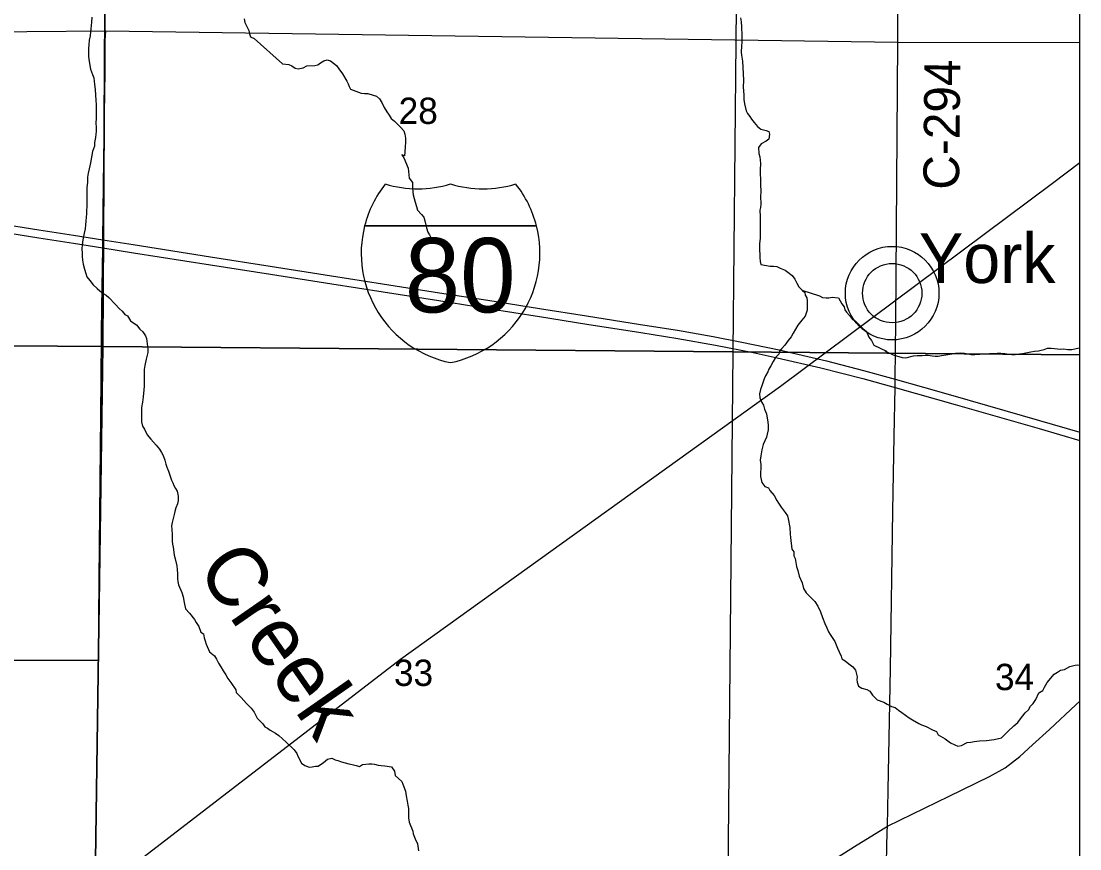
# Model space of a CAD drawing. Extents: x -8.5 to 18.7, y -20.3 to 7.
# Drawn here: x 15.375 to 18.741, y 1.627 to 4.26 of the extents above; entities that cross this region are included whole.
import ezdxf

# ---------------------------------------------------------------- set-up
doc = ezdxf.new("R2010")
doc.units = 0
for name, color, linetype in [('Default', 7, 'Continuous'), ('GM_X_Corporation', 7, 'Continuous'), ('GM_X_County_Road', 7, 'Continuous'), ('GM_X_County_Road_Text', 7, 'Continuous'), ('GM_X_Interstate_Location', 7, 'Continuous'), ('GM_X_Interstate_Route', 7, 'Continuous'), ('GM_X_Interstate_Shield', 7, 'Continuous'), ('GM_X_Minor_River', 7, 'Continuous'), ('GM_X_Minor_River_Text', 7, 'Continuous'), ('GM_X_Rail_Line', 7, 'Continuous'), ('GM_X_Section', 7, 'Continuous'), ('GM_X_Section_Text', 7, 'Continuous'), ('GM_X_State_Route', 7, 'Continuous'), ('GM_X_Township_Road', 7, 'Continuous'), ('GM_X_Unincorporated', 7, 'Continuous'), ('GM_X_Unincorporated_Location', 7, 'Continuous'), ('GM_X_Unincorporated_Text', 7, 'Continuous'), ('SH_Cut_Line', 7, 'Continuous')]:
    doc.layers.add(name, color=color, linetype=linetype)

msp = doc.modelspace()

# ---------------------------------------------------------------- linework, layer by layer
at = {"layer": 'Default'}
for points in [[(18.7413, 3.1985), (18.7413, 5.1812), (17.6568, 5.1811), (17.6382, 3.208)], [(18.7413, 1.196), (18.7413, 3.1985), (17.6382, 3.208), (17.6187, 1.2053)]]:
    msp.add_lwpolyline(points, close=True, dxfattribs=at)
at = {"layer": 'GM_X_Corporation'}
msp.add_lwpolyline([(18.7413, 1.1834), (18.7413, 6.938), (11.7049, 6.938), (11.6732, 5.0475), (11.6689, 4.6186), (11.6686, 4.5917), (11.6653, 4.2586), (11.64, 3.2551), (11.6132, 2.2462), (11.5871, 1.2389), (13.587, 1.2234), (15.5804, 1.208), (17.3261, 1.1944), (18.0915, 1.1885)], close=True, dxfattribs=at)
at = {"layer": 'GM_X_County_Road'}
for points in [[(18.1302, 1.6994), (18.1318, 1.8143), (18.1389, 2.2013), (18.1465, 2.7014), (18.1506, 2.9396), (18.1537, 3.095), (18.1543, 3.1212), (18.1565, 3.3035), (18.1628, 4.1924), (18.1717, 5.8471), (18.1598, 6.938)], [(18.1003, 1.2079), (18.1028, 1.2134), (18.1171, 1.2442), (18.1227, 1.2661), (18.1241, 1.304), (18.1261, 1.4721), (18.1267, 1.5823), (18.1273, 1.6332), (18.1285, 1.6812), (18.1302, 1.6994)]]:
    msp.add_lwpolyline(points, dxfattribs=at)
at = {"layer": 'GM_X_Interstate_Route'}
for points in [[(15.2513, 3.6247), (15.4311, 3.5964), (15.5415, 3.579), (15.6351, 3.5645), (15.7311, 3.549), (15.9769, 3.5106), (16.1667, 3.4809), (16.3624, 3.4499), (16.5241, 3.4243), (16.705, 3.3957), (16.8596, 3.3719), (17.0229, 3.3463), (17.1727, 3.3224), (17.344, 3.2954), (17.4621, 3.2766), (17.5754, 3.2566), (17.6667, 3.2389), (17.7858, 3.2139), (17.936, 3.179), (18.0537, 3.149), (18.1543, 3.1212), (18.2447, 3.0951), (18.3302, 3.0709), (18.4475, 3.0374), (18.6134, 2.9894), (18.7413, 2.9528)], [(15.2523, 3.5988), (15.4321, 3.5705), (15.5415, 3.5537), (15.6346, 3.5389), (15.7321, 3.5231), (15.9779, 3.4847), (16.1677, 3.455), (16.3635, 3.424), (16.5267, 3.3986), (16.7029, 3.371), (16.8606, 3.346), (17.0239, 3.3204), (17.1737, 3.2965), (17.3451, 3.2694), (17.4631, 3.2506), (17.5828, 3.2292), (17.7027, 3.2055), (17.779, 3.1891), (17.9174, 3.1571), (18.0518, 3.1233), (18.1537, 3.095), (18.3446, 3.04), (18.6122, 2.964), (18.7413, 2.9264)]]:
    msp.add_lwpolyline(points, dxfattribs=at)
at = {"layer": 'GM_X_Interstate_Shield'}
for p, q in [((16.4673, 3.6086), (17.0138, 3.6086)), ((17.0138, 3.6086), (16.4673, 3.6086)), ((17.0138, 3.6086), (16.4673, 3.6086))]:
    msp.add_line(p, q, dxfattribs=at)
for centre, start, end in [((16.8116, 3.5215), 141.669, 165.8066), ((16.6368, 4.0814), 253.0091, 286.9909), ((16.8443, 4.0814), 253.0091, 286.9909), ((16.6695, 3.5215), 14.1934, 38.331), ((16.8116, 3.5215), 165.8066, 258.463), ((16.6695, 3.5215), 281.537, 14.1934)]:
    msp.add_arc(centre, 0.3551, start, end, dxfattribs=at)
at = {"layer": 'GM_X_Minor_River'}
msp.add_line((18.7353, 2.212), (18.7413, 2.2119), dxfattribs=at)
for points in [[(15.6001, 4.2721), (15.5986, 4.2561), (15.5979, 4.2462), (15.5972, 4.2356), (15.5957, 4.2257), (15.5943, 4.2135), (15.5921, 4.1991), (15.5906, 4.1846), (15.5892, 4.1725), (15.5892, 4.1634), (15.59, 4.1489), (15.5909, 4.1391), (15.5924, 4.1246), (15.5963, 4.1072), (15.6017, 4.0905), (15.6063, 4.0791), (15.6079, 4.0692), (15.6087, 4.0586), (15.6103, 4.0427), (15.6119, 4.0244), (15.6128, 4.0085), (15.6136, 3.9933), (15.6138, 3.9523), (15.6131, 3.934), (15.614, 3.9234), (15.614, 3.909), (15.6126, 3.8998), (15.6118, 3.89), (15.6089, 3.874), (15.6082, 3.8626), (15.6022, 3.8451), (15.5963, 3.8086), (15.5918, 3.7903), (15.5881, 3.7759), (15.5867, 3.7637), (15.586, 3.7478), (15.5846, 3.7295), (15.5839, 3.7151), (15.5839, 3.7045), (15.5847, 3.6961), (15.584, 3.6847), (15.5841, 3.6695), (15.5834, 3.6589), (15.5827, 3.6467), (15.582, 3.6368), (15.5813, 3.6231), (15.5798, 3.6117), (15.5784, 3.5996), (15.5762, 3.5851), (15.571, 3.5638), (15.5695, 3.5479), (15.5688, 3.5357), (15.5689, 3.522), (15.5697, 3.5114), (15.5705, 3.4993), (15.5721, 3.4871), (15.5767, 3.4712), (15.5814, 3.4568), (15.5837, 3.4461), (15.5936, 3.4348), (15.6043, 3.4212), (15.6173, 3.4098), (15.6257, 3.4015), (15.6363, 3.3932), (15.6455, 3.3879), (15.6539, 3.3804), (15.6745, 3.36), (15.6875, 3.3456), (15.6966, 3.3373), (15.705, 3.3267), (15.7134, 3.3229), (15.7233, 3.307), (15.7332, 3.2995), (15.7424, 3.2934), (15.7523, 3.2805), (15.7622, 3.2715), (15.7706, 3.2594), (15.7737, 3.2503), (15.7784, 3.2169), (15.7777, 3.2055), (15.7733, 3.1849), (15.7681, 3.1644), (15.7666, 3.1522), (15.766, 3.1325), (15.766, 3.1157), (15.7661, 3.099), (15.7654, 3.0876), (15.7633, 3.0648), (15.7611, 3.0481), (15.7581, 3.0306), (15.7582, 3.0185), (15.7575, 2.9964), (15.7576, 2.9858), (15.7615, 2.9714), (15.7676, 2.9623), (15.776, 2.9441), (15.7875, 2.9297), (15.805, 2.9116)], [(16.0845, 4.2668), (16.0868, 4.2554), (16.0929, 4.2425), (16.0991, 4.2304), (16.1014, 4.219), (16.1045, 4.2099), (16.1159, 4.2046), (16.2059, 4.1245), (16.2264, 4.1216), (16.2363, 4.1178), (16.247, 4.1103), (16.2561, 4.108), (16.272, 4.1111), (16.2841, 4.118), (16.3092, 4.1182), (16.3183, 4.1205), (16.3266, 4.1273), (16.3379, 4.1335), (16.3478, 4.1366), (16.3584, 4.1336), (16.3775, 4.1192), (16.3859, 4.1079), (16.3974, 4.092), (16.4104, 4.0692), (16.415, 4.0602), (16.4181, 4.0518), (16.4227, 4.0435), (16.4569, 4.0307), (16.4668, 4.0292), (16.4774, 4.0293), (16.4941, 4.0248), (16.5048, 4.0211), (16.5147, 4.0128), (16.5216, 4.0014), (16.53, 3.9855), (16.5384, 3.9718), (16.5453, 3.9605), (16.5514, 3.9499), (16.5621, 3.9416), (16.5812, 3.9227), (16.5919, 3.9106), (16.595, 3.9007), (16.5973, 3.8878), (16.5974, 3.8734), (16.5967, 3.8612), (16.5953, 3.843), (16.5938, 3.8316), (16.5854, 3.8346), (16.5916, 3.8247), (16.6054, 3.7921)], [(17.6628, 4.2704), (17.6644, 4.2575), (17.6653, 4.2416), (17.6669, 4.2142), (17.6662, 4.2013), (17.6663, 4.1922), (17.6656, 4.1816), (17.6649, 4.161), (17.6657, 4.1512)], [(17.6657, 4.1512), (17.6689, 4.1322), (17.6697, 4.1124), (17.6713, 4.0919), (17.6722, 4.0722), (17.6708, 4.0501), (17.6732, 4.0258), (17.6733, 4.0106), (17.6748, 3.997), (17.681, 3.975), (17.6849, 3.9659), (17.6918, 3.9568), (17.6979, 3.9477), (17.7063, 3.9371), (17.7162, 3.9242), (17.7276, 3.9167), (17.7444, 3.9115), (17.7527, 3.9085), (17.7543, 3.9001), (17.7528, 3.8841), (17.7438, 3.878), (17.7279, 3.8696), (17.7196, 3.8582), (17.7212, 3.8384), (17.7243, 3.8286), (17.7251, 3.8179), (17.7259, 3.8065), (17.7252, 3.7868), (17.7253, 3.7723), (17.7261, 3.7594), (17.7262, 3.7419), (17.7271, 3.7154), (17.7264, 3.7032), (17.7266, 3.6781), (17.7258, 3.6667), (17.7244, 3.6584), (17.7245, 3.6379), (17.7253, 3.6173), (17.7255, 3.5809), (17.7248, 3.5687), (17.7226, 3.5528), (17.7227, 3.5315), (17.7243, 3.5171), (17.7244, 3.5079), (17.7252, 3.4958), (17.7275, 3.4859), (17.7564, 3.4807), (17.7678, 3.48), (17.7784, 3.4793), (17.7883, 3.4741), (17.8043, 3.4673), (17.8127, 3.4612), (17.8264, 3.4507), (17.8348, 3.4393), (17.8417, 3.4264), (17.8478, 3.4143), (17.8585, 3.4037), (17.8669, 3.3962), (17.8677, 3.3878), (17.8731, 3.3795), (17.8739, 3.3704), (17.8747, 3.3491), (17.874, 3.3407), (17.868, 3.3217), (17.8575, 3.3088), (17.8446, 3.2927), (17.8371, 3.2798), (17.8296, 3.2676), (17.8236, 3.2562), (17.8138, 3.244), (17.8032, 3.2295), (17.7926, 3.218), (17.7866, 3.2096), (17.7844, 3.2005), (17.7738, 3.1898), (17.7663, 3.1769), (17.7587, 3.1639), (17.7527, 3.1533), (17.7497, 3.1441), (17.7422, 3.1319), (17.7377, 3.122), (17.7317, 3.103), (17.7257, 3.0878), (17.7227, 3.0741), (17.7243, 3.0612), (17.7305, 3.0468), (17.7351, 3.0385), (17.7389, 3.0256), (17.7451, 3.0104), (17.7498, 2.9838), (17.7506, 2.9747), (17.7506, 2.9595), (17.7469, 2.9458), (17.7454, 2.9367), (17.7394, 2.9253), (17.7349, 2.9131), (17.7305, 2.8964), (17.7275, 2.8774), (17.7253, 2.8637), (17.7269, 2.8492), (17.727, 2.8378)], [(16.6054, 3.7921), (16.6093, 3.7602), (16.6193, 3.7466), (16.6194, 3.7291), (16.6202, 3.717), (16.6217, 3.7078), (16.6279, 3.6843), (16.6318, 3.6699), (16.6357, 3.6585), (16.6486, 3.6449), (16.6555, 3.6358), (16.6586, 3.6244), (16.6617, 3.6108), (16.664, 3.6024), (16.6679, 3.5888), (16.674, 3.5797), (16.6794, 3.5698), (16.6863, 3.5608)], [(17.8577, 3.4045), (17.9133, 3.3857), (17.9232, 3.3812), (17.9345, 3.3798), (17.9437, 3.3798), (17.9535, 3.3821), (17.974, 3.38), (17.9848, 3.361), (17.9916, 3.3512), (17.994, 3.3421), (17.9993, 3.3337), (18.0092, 3.3239), (18.0184, 3.311), (18.0268, 3.3065), (18.0512, 3.2823), (18.0626, 3.2725), (18.0703, 3.2543), (18.0787, 3.2445), (18.0856, 3.2316), (18.0866, 3.2291)], [(18.1272, 3.2091), (18.087, 3.2286)], [(18.1214, 3.2116), (18.148, 3.1984), (18.1587, 3.1955), (18.1769, 3.1895), (18.1876, 3.1888), (18.2126, 3.1949), (18.224, 3.1965), (18.2399, 3.1966), (18.2498, 3.1974), (18.2596, 3.1974), (18.2718, 3.1952), (18.2817, 3.1938), (18.2908, 3.1938), (18.3014, 3.1961), (18.3158, 3.1985), (18.334, 3.2016), (18.3462, 3.2039), (18.3629, 3.2048), (18.3743, 3.2033), (18.3857, 3.2011), (18.3963, 3.1996), (18.4077, 3.1997), (18.4229, 3.2005), (18.4396, 3.2013), (18.454, 3.2029), (18.4654, 3.203), (18.4783, 3.2038), (18.4904, 3.2039), (18.5033, 3.2032), (18.5155, 3.2009), (18.5254, 3.1995), (18.536, 3.1995), (18.5496, 3.2011), (18.5595, 3.2027), (18.5701, 3.205), (18.5853, 3.2081), (18.5967, 3.2097), (18.6096, 3.2113), (18.6187, 3.2128), (18.6278, 3.2159), (18.6384, 3.2198), (18.6505, 3.2198), (18.6612, 3.2183), (18.6703, 3.2176), (18.6801, 3.2169), (18.6893, 3.217), (18.7029, 3.2155), (18.7158, 3.2156), (18.7257, 3.2179), (18.7393, 3.2202), (18.7413, 3.2204)], [(15.805, 2.9116), (15.8157, 2.8979), (15.8218, 2.8881), (15.8265, 2.8782), (15.8318, 2.8631), (15.8357, 2.8509), (15.8388, 2.8411), (15.8442, 2.8289), (15.8534, 2.8001), (15.8573, 2.791), (15.8611, 2.7827), (15.8665, 2.7728), (15.8711, 2.7645), (15.8749, 2.7493), (15.8742, 2.7356), (15.872, 2.725), (15.8675, 2.7113), (15.8645, 2.7006), (15.8623, 2.6907), (15.8578, 2.674), (15.8556, 2.6649), (15.8534, 2.655), (15.8542, 2.6444), (15.8558, 2.6254), (15.8559, 2.6056), (15.8567, 2.5965), (15.859, 2.5866), (15.8606, 2.5707), (15.8622, 2.5616), (15.8653, 2.5494), (15.8707, 2.5274), (15.8716, 2.5145), (15.8724, 2.5031), (15.8725, 2.4864), (15.8733, 2.4773), (15.8756, 2.4674), (15.8863, 2.4424), (15.8902, 2.4288), (15.8933, 2.4105), (15.898, 2.3901), (15.911, 2.3764), (15.9262, 2.3568), (15.9316, 2.3469), (15.94, 2.3348), (15.9469, 2.3166), (15.9553, 2.3106), (15.9577, 2.2984), (15.96, 2.2885), (15.9631, 2.2779), (15.9746, 2.2537), (15.9898, 2.2416), (15.9967, 2.2302), (16.0029, 2.2181), (16.0098, 2.206), (16.0174, 2.1938), (16.0266, 2.1802), (16.0327, 2.1688), (16.0419, 2.156), (16.0579, 2.1333), (16.0595, 2.1249), (16.0748, 2.1083), (16.0916, 2.0893), (16.1068, 2.0742), (16.116, 2.0621), (16.126, 2.0424), (16.1435, 2.0243), (16.1504, 2.0152), (16.1588, 2.0114), (16.1672, 2.0046), (16.1839, 1.9948), (16.1946, 1.9873), (16.2068, 1.9767), (16.2182, 1.9669), (16.2434, 1.9419), (16.2518, 1.9306), (16.2549, 1.9222), (16.2664, 1.9002), (16.277, 1.8919), (16.2907, 1.8867), (16.3006, 1.8882), (16.3112, 1.8906), (16.3196, 1.8906), (16.337, 1.9021), (16.3491, 1.9128), (16.3635, 1.9159), (16.3734, 1.9099), (16.3825, 1.9084), (16.3939, 1.9039), (16.4175, 1.8979), (16.4281, 1.8957), (16.4403, 1.8919), (16.4509, 1.889), (16.4608, 1.8958), (16.4805, 1.8975), (16.4904, 1.8975), (16.4987, 1.8968), (16.5101, 1.8938), (16.52, 1.8923), (16.5321, 1.8909), (16.5527, 1.8879), (16.5626, 1.8743)], [(17.727, 2.8378), (17.7263, 2.8234), (17.7256, 2.8112), (17.7302, 2.7923), (17.7394, 2.7794), (17.7516, 2.7749), (17.7554, 2.7666), (17.7691, 2.7514), (17.7776, 2.7355), (17.7837, 2.7264), (17.7913, 2.7136), (17.8043, 2.6969), (17.812, 2.6863), (17.8143, 2.6764), (17.8198, 2.6491), (17.8206, 2.6278), (17.8214, 2.6172), (17.8262, 2.5808), (17.8323, 2.5717), (17.8324, 2.5588), (17.8362, 2.5504), (17.8409, 2.5254), (17.8447, 2.5125), (17.8494, 2.4943), (17.8586, 2.4738), (17.8632, 2.4556), (17.8709, 2.4419), (17.8991, 2.414), (17.9083, 2.3988), (17.9168, 2.3814), (17.9237, 2.3632), (17.9306, 2.3442), (17.9368, 2.3298), (17.9421, 2.3177), (17.9475, 2.3086), (17.9536, 2.2995), (17.962, 2.2866), (17.9705, 2.2654), (17.9759, 2.2533), (17.982, 2.2404), (17.9851, 2.2313), (17.995, 2.2252), (18.0072, 2.2154), (18.0194, 2.2064), (18.0278, 2.195), (18.0316, 2.1829), (18.0332, 2.1745), (18.0325, 2.1662), (18.0333, 2.157), (18.0379, 2.1449), (18.0486, 2.1381), (18.0638, 2.1336), (18.0737, 2.1291), (18.0821, 2.1162), (18.0973, 2.1011), (18.1179, 2.0936), (18.1293, 2.0876), (18.143, 2.0801), (18.1544, 2.0763), (18.1643, 2.0688), (18.175, 2.0605), (18.1986, 2.0439), (18.2093, 2.0378), (18.2291, 2.0258), (18.2382, 2.022), (18.2526, 2.0168), (18.2732, 2.0062), (18.2854, 2.0002), (18.2907, 1.9896), (18.3128, 1.9768), (18.3303, 1.9639), (18.344, 1.9579), (18.3532, 1.9542), (18.3653, 1.9558), (18.3835, 1.9657), (18.3949, 1.9665), (18.4055, 1.9681), (18.4222, 1.9705), (18.4449, 1.9713), (18.4685, 1.9745), (18.4927, 1.9807), (18.5124, 2.0005), (18.5313, 2.0181), (18.5441, 2.0295), (18.5524, 2.0402), (18.5675, 2.0593), (18.5781, 2.0692), (18.5841, 2.0814), (18.5932, 2.089), (18.6015, 2.102), (18.6105, 2.1233), (18.6241, 2.131), (18.6293, 2.1416), (18.6376, 2.1561), (18.6595, 2.1828), (18.6701, 2.1889), (18.6799, 2.1951), (18.6921, 2.1981), (18.7095, 2.2073), (18.7262, 2.2112), (18.7353, 2.212)], [(16.5626, 1.8743), (16.5642, 1.8606), (16.5855, 1.841), (16.5886, 1.8326), (16.5971, 1.8106), (16.5994, 1.7955), (16.6026, 1.7788), (16.6049, 1.7666), (16.6065, 1.7552), (16.6073, 1.737), (16.6074, 1.7256), (16.609, 1.7119), (16.6205, 1.6831), (16.6213, 1.6748), (16.6282, 1.6588), (16.6359, 1.6429), (16.6383, 1.6209)]]:
    msp.add_lwpolyline(points, dxfattribs=at)
at = {"layer": 'GM_X_Rail_Line'}
msp.add_lwpolyline([(9.8265, -3.4832), (9.9554, -3.3738), (10.2236, -3.1276), (10.7275, -2.6809), (11.4033, -2.0504), (11.764, -1.7469), (11.984, -1.5594), (12.7991, -0.8182), (13.6363, -0.0615), (14.079, 0.3384), (14.2522, 0.47), (14.4319, 0.6106), (14.5413, 0.6862), (15.5503, 1.4365), (16.5816, 2.231), (17.7899, 3.0985), (18.6545, 3.7446), (18.7413, 3.8103)], dxfattribs=at)
at = {"layer": 'GM_X_Section'}
for points in [[(15.6471, 5.1817), (15.6347, 3.2252), (13.6222, 3.2394), (13.6421, 5.1822)], [(17.6568, 5.1811), (17.6382, 3.208), (15.6347, 3.2252), (15.6471, 5.1817)], [(13.6222, 3.2394), (15.6347, 3.2252), (15.6061, 1.2188), (15.5788, 1.2174), (13.5966, 1.2307)], [(17.6382, 3.208), (17.6187, 1.2053), (17.5899, 1.2047), (15.6061, 1.2188), (15.6347, 3.2252)]]:
    msp.add_lwpolyline(points, close=True, dxfattribs=at)
at = {"layer": 'GM_X_State_Route'}
msp.add_lwpolyline([(17.0758, 1.0347), (17.174, 1.0971), (17.3266, 1.1933), (17.3392, 1.2012), (18.0252, 1.6343), (18.1302, 1.6994), (18.326, 1.7949), (18.4545, 1.8571), (18.5035, 1.8849), (18.5504, 1.9208), (18.5913, 1.9576), (18.6446, 2.0067), (18.7288, 2.0849), (18.7413, 2.0972)], dxfattribs=at)
at = {"layer": 'GM_X_Township_Road'}
for points in [[(13.6358, 4.2197), (13.791, 4.2171), (14.2207, 4.2153), (14.4137, 4.2139), (14.6081, 4.2161), (14.911, 4.2204), (15.1413, 4.2248), (15.645, 4.2292), (18.1628, 4.1924), (18.7413, 4.192)], [(15.6395, 3.8957), (15.6428, 4.1001), (15.642, 4.1679), (15.6427, 4.1984), (15.645, 4.2292)], [(15.6307, 3.2676), (15.6324, 3.3491), (15.6346, 3.5389), (15.6351, 3.5645), (15.6368, 3.7399), (15.6394, 3.8917), (15.6395, 3.8957)], [(15.6209, 2.2271), (15.6237, 2.4859), (15.6288, 3.0042), (15.6303, 3.2501), (15.6307, 3.2676)], [(13.5934, 2.2286), (13.6134, 2.2284), (13.8466, 2.2271), (15.6209, 2.2271)], [(15.5918, 1.2263), (15.5976, 1.2357), (15.6042, 1.2483), (15.6077, 1.2624), (15.6088, 1.2819), (15.6091, 1.358), (15.6209, 2.2271)]]:
    msp.add_lwpolyline(points, dxfattribs=at)
at = {"layer": 'GM_X_Unincorporated'}
for radius in [0.1488, 0.0943]:
    msp.add_circle((18.1447, 3.3946), radius, dxfattribs=at)
at = {"layer": 'GM_X_Unincorporated_Location'}
msp.add_line((18.1447, 3.3946), (18.1447, 3.3946), dxfattribs=at)
at = {"layer": 'SH_Cut_Line'}
msp.add_lwpolyline([(18.7413, -10.9039), (18.7413, 6.938), (-8.4587, 6.938)], dxfattribs=at)

# ---------------------------------------------------------------- texts
at = {"layer": 'GM_X_County_Road_Text'}
msp.add_text('C-294', height=0.11364, rotation=89.4494, dxfattribs=at).set_placement((18.3572, 3.7233))
at = {"layer": 'GM_X_Interstate_Location'}
for s in ['-', '.', ',']:
    msp.add_text(s, height=0.000379, dxfattribs=at).set_placement((16.7405, 3.4575))
msp.add_text('80', height=0.000379, rotation=0, dxfattribs=at).set_placement((16.6631, 3.3791))
at = {"layer": 'GM_X_Interstate_Shield'}
msp.add_text('80', height=0.23674, dxfattribs=at).set_placement((16.5951, 3.3334))
at = {"layer": 'GM_X_Minor_River_Text'}
msp.add_text('Creek', height=0.18951, rotation=304.7721, dxfattribs=at).set_placement((15.9301, 2.5177))
at = {"layer": 'GM_X_Section_Text'}
for s, p in [('28', (16.5756, 3.9328)), ('33', (16.5606, 2.1453)), ('34', (18.4715, 2.132))]:
    msp.add_text(s, height=0.08371, rotation=0, dxfattribs=at).set_placement(p)
at = {"layer": 'GM_X_Unincorporated_Text'}
msp.add_text('York', height=0.15795, rotation=0, dxfattribs=at).set_placement((18.2298, 3.4268))

doc.saveas('drawing.dxf')
